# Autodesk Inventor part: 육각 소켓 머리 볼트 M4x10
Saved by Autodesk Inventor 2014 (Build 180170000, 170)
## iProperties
Created: 2025-02
Part Number: 육각 소켓 머리 볼트 M4x10
Material: 강철, 연강
Document SubType Name: Modeling
Designer: dg
Density: 7.86 g/cm^3
Appearance: 강철
Mass: 2.0371 g
Surface Area: 3.0572 cm^2
Volume: 0.259174 cm^3
Author: jhkim
Description: 6각머리 태핑 나사
Creation Date: 2025-01-06
Sending System: Autodesk Inventor 2025
Preprocessor: ST-DEVELOPER v20
Author: dg
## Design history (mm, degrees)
node "육각 소켓 머리 볼트 M4x101"
body "Solid1"
node "기준1"
